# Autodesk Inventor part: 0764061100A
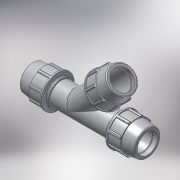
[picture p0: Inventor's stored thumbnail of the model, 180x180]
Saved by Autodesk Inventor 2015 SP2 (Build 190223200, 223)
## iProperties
Created: 2017-02
Part Number: 0764061100A
Material: PVC-Piping
Description: PLASSON 45° TEE 110-110-110
Document SubType Name: Modeling
Designer: KIM
Mass: 92.6774 g
Surface Area: 199.44 cm^2
Volume: 66.1981 cm^3
Density: 1.4 g/cm^3
Appearance: Smooth - White
Author: KIM
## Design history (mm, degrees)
derived "87640.ipt"
feature "Solid1::87640.ipt"
feature "Solid3::87640.ipt"
tag "TaggingFeature1"
body "Solid1"
other parameters: "d4" = 26.04167, "d5" = 62.5, "d7" = 181, "d11" = 10.41667, "d13" = 120 deg, "d14" = 143, "d15" = 8 deg, "d16" = 144.8, "d18" = 5.5, "d19" = 35 deg, "d20" = 17.5 deg, "d21" = 168.33, "d23" = 0, "d25" = 360 deg, "d27" = 3.62, "d33" = 2.2, "d42" = 75, "d43" = 5.43, "d46" = 3.3, "d68" = 9.375, "d91" = 126.7, "d93" = 194, "d95" = 99, "d134" = 312.5, "d138" = 45 deg, "d141" = 284, "d144" = 0, "d146" = 0, "d150" = 5.5, "d158" = 2.2, "d159" = 7.24, "d160" = 0, "d165" = 368.6, "d166" = 168.33, "d167" = 35 deg, "d168" = 17.5 deg, "d170" = 0, "d172" = 360 deg, "d174" = 5.43, "d177" = 3.62, "d180" = 7.24, "d181" = 0, "E_" = 181, "A_" = 284, "l_" = 194, "H_" = 625
